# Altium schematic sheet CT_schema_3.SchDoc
size 334 x 183 mm
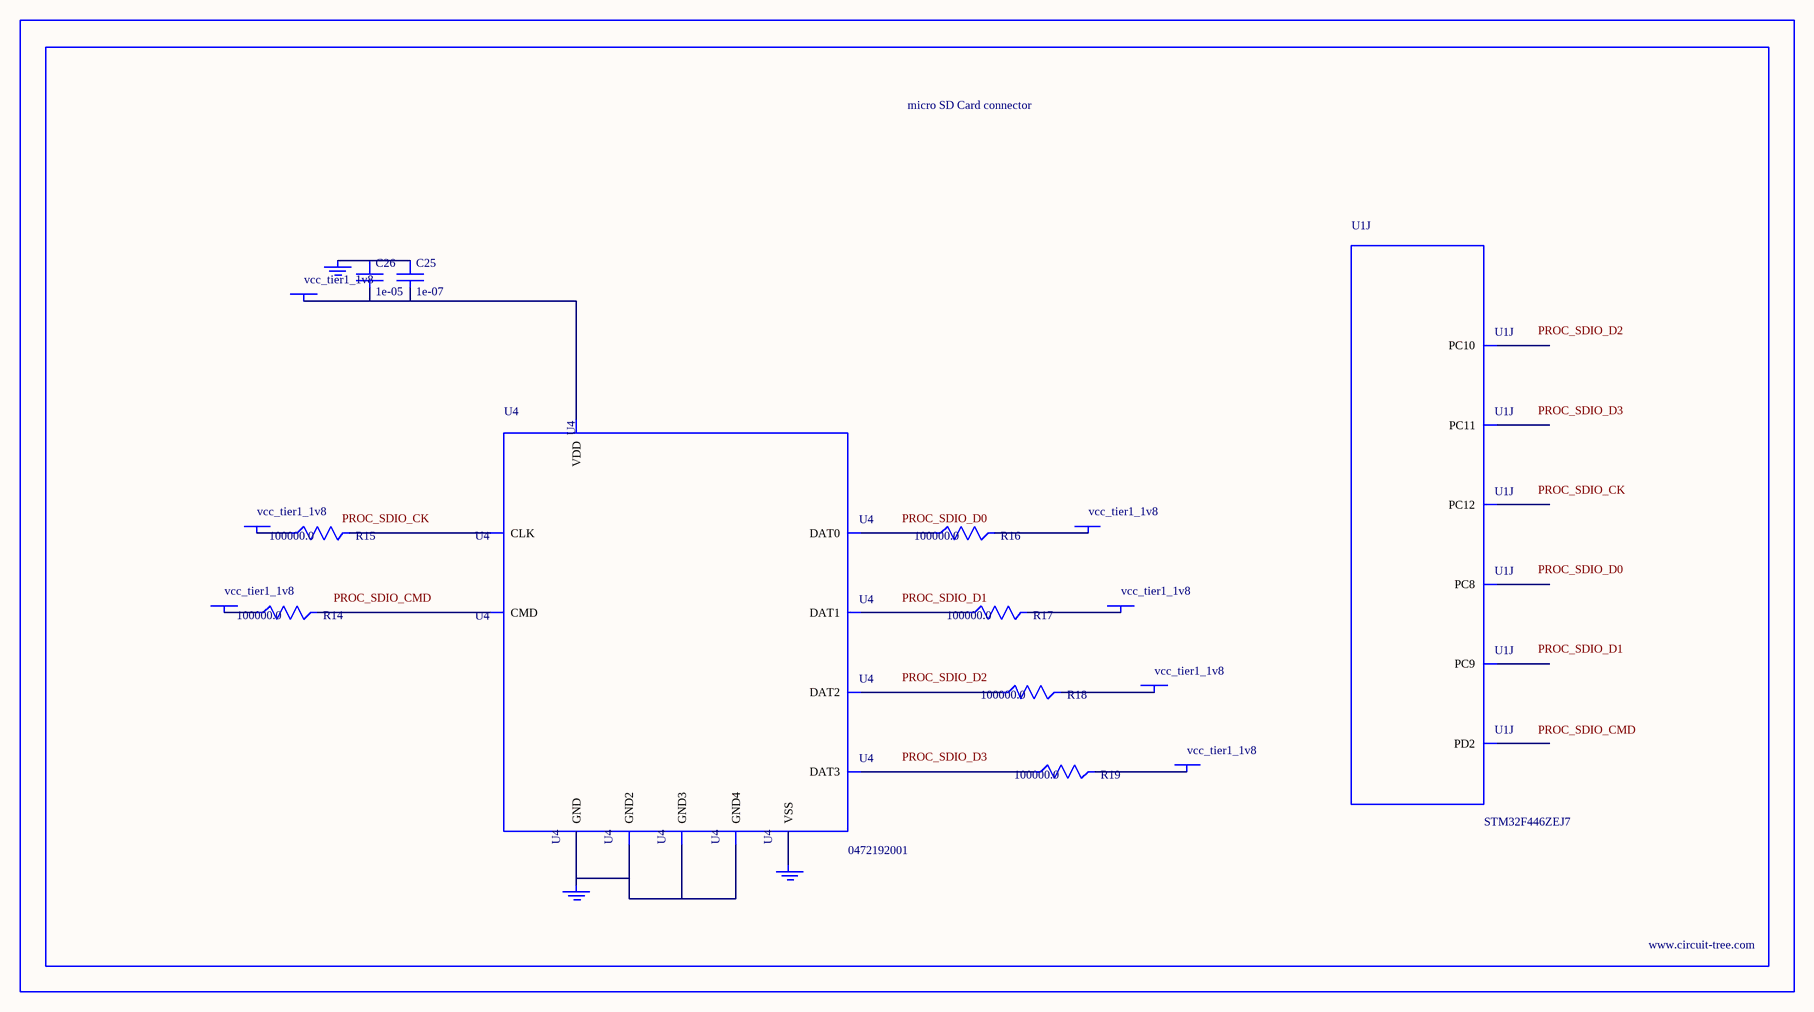
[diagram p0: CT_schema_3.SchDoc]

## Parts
BORDER2  (no value)
C25  1e-07  [C0402]
C26  1e-05  [C0805]
GND_INSTANCE_2_0  (no value)
GND_INSTANCE_2_1  (no value)
GND_INSTANCE_2_2  (no value)
POWER_INSTANCE_2_0  vcc_tier1_1v8
POWER_INSTANCE_2_1  vcc_tier1_1v8
POWER_INSTANCE_2_2  vcc_tier1_1v8
POWER_INSTANCE_2_3  vcc_tier1_1v8
POWER_INSTANCE_2_4  vcc_tier1_1v8
POWER_INSTANCE_2_5  vcc_tier1_1v8
POWER_INSTANCE_2_6  vcc_tier1_1v8
R14  100000.0  [R0603]
R15  100000.0  [R0603]
R16  100000.0  [R0603]
R17  100000.0  [R0603]
R18  100000.0  [R0603]
R19  100000.0  [R0603]
U1  STM32F446ZEJ7  [UFBGA144]  (part J of 12)
U4  0472192001  [MOLEX_47219-2001]

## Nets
NetC25_1: C25.1 C26.1 GND_INSTANCE_2_0.0(GND)
NetC25_2: C25.2 C26.2 POWER_INSTANCE_2_3.0(PWR) U4.4(VDD)
NetGND_INSTANCE_2_1_0: GND_INSTANCE_2_1.0(GND) U4.6(VSS)
NetGND_INSTANCE_2_2_0: GND_INSTANCE_2_2.0(GND) U4.G1(GND) U4.G2(GND2) U4.G3(GND3) U4.G4(GND4)
NetPOWER_INSTANCE_2_0_0: POWER_INSTANCE_2_0.0(PWR) R18.2
NetPOWER_INSTANCE_2_1_0: POWER_INSTANCE_2_1.0(PWR) R19.2
NetPOWER_INSTANCE_2_2_0: POWER_INSTANCE_2_2.0(PWR) R14.1
NetPOWER_INSTANCE_2_4_0: POWER_INSTANCE_2_4.0(PWR) R15.1
NetPOWER_INSTANCE_2_5_0: POWER_INSTANCE_2_5.0(PWR) R16.2
NetPOWER_INSTANCE_2_6_0: POWER_INSTANCE_2_6.0(PWR) R17.2
NetR14_2: R14.2 U4.3(CMD)
NetR15_2: R15.2 U4.5(CLK)
NetR16_1: R16.1 U4.7(DAT0)
NetR17_1: R17.1 U4.8(DAT1)
NetR18_1: R18.1 U4.1(DAT2)
NetR19_1: R19.1 U4.2(DAT3)

Not connected (* = marked no-connect by the designer): U1 B10(PC11) B11(PC10) C10(PC12) E9(PD2) E11(PC9) F11(PC8)

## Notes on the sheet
- Labels drawn without touching a wire or pin: PROC_SDIO_CK, PROC_SDIO_CMD, PROC_SDIO_D0, PROC_SDIO_D1, PROC_SDIO_D2, PROC_SDIO_D3

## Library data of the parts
BORDER2 = BORDER_PAGE2
C25 = C0402C104K3RACTU
C26 = C0805C106K8RACTU
GND_INSTANCE_2_0-GND_INSTANCE_2_2 = GND
POWER_INSTANCE_2_0-POWER_INSTANCE_2_6 = PWR
R14-R19 = RC0603JR-07100KL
